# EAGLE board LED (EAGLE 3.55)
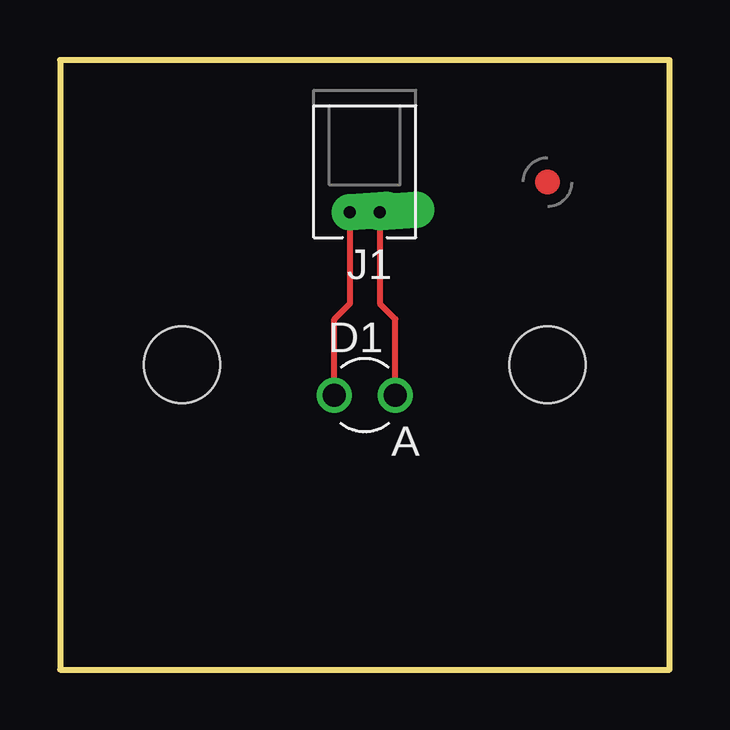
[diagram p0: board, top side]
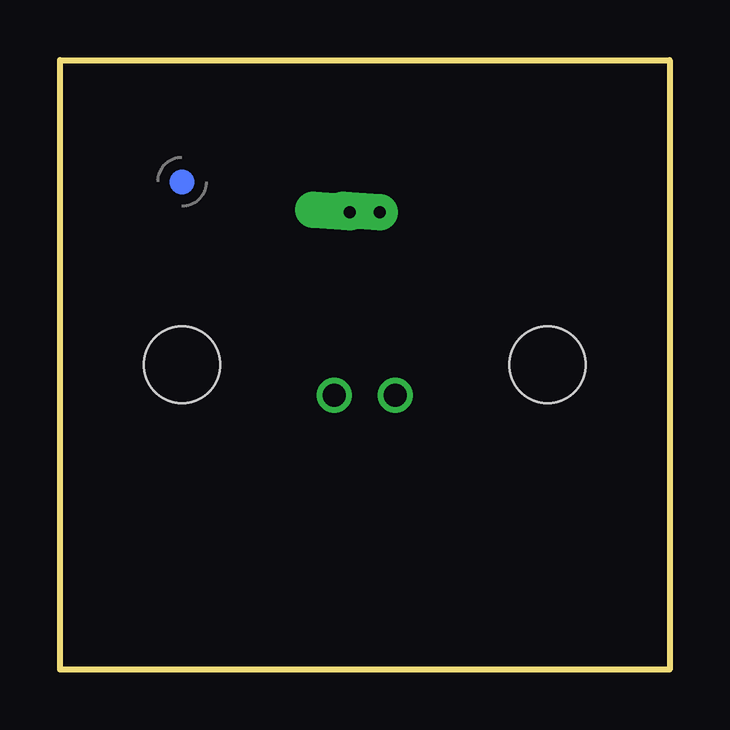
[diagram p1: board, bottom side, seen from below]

Size 25.4 x 25.4 mm. Coordinates in mm from the lower left corner, seen from the top.
Outline: 0,0 25.4,0 25.4,25.4 0,25.4 0,0
Copper layers used: Top

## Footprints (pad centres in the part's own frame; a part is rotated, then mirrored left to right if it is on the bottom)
 = drill 0.965 pad 1.473 round:  -1.27,0;  1.27,0
048-2 = drill 0.508 pad 1.524 offset:  -0.625,0;  0.625,0
OLE125 = hole 3.175: 0,0

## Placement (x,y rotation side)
D1  L934GD  []  12.7,11.43 180 top
FID1  [DUCIAL]  20.32,20.32 0 top
J1  51021-0200  [048-2]  12.7,19.05 0 top
U$3  [LX]  not placed on the board
U$4  [L+]  not placed on the board
U$5  [LSQTOP]  not placed on the board
U$6  [OLE125]  5.08,12.7 0 top
U$7  [OLE125]  20.32,12.7 0 top
XU$3  [EETB]  not placed on the board
XU$4  [CFIELD]  not placed on the board
XU$5  [BNOTES]  not placed on the board
XU$6  [BWTI]  not placed on the board
XU$7  [B1INK]  not placed on the board
XU$8  [R2-062]  not placed on the board

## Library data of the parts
D1 J1 = Parts
FID1 U$3-U$7 XU$5-XU$8 = Mech
XU$3 XU$4 = Sheets

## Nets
N$1: D1. J1.
N$2: D1. J1.

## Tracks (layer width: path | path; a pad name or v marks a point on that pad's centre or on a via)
N$1
  Top 0.254: J1. 13.32,15.25 13.97,14.61 13.97,11.43
N$2
  Top 0.254: 12.07,19.05 12.07,15.25 11.43,14.61 D1.

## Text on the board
Measures: 0.000 | 0.200 | 1.000 | 0.000 | 0.000 | 0.000 | 0.000 | 0.000 | 1.000
Document: SYM | SIZE | TYPE | CNT | A | NPT | 2 | PTH | 2 | PTH | 2 | TOTAL | 6 | A | 1:1 | B | 1/1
